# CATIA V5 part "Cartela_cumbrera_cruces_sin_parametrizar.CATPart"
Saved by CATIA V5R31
Part number: Cartela_param_pilar_dintel
Material "PLA": density 1240 kg/m3, Young's modulus 3.2e+09 Pa, Poisson ratio 0.331, thermal expansion 6.84e-05 1/K
Bounding box of the stored display mesh (mm): x -3.75 to 9.35, y -3.749 to 34.731, z -2 to 2
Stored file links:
  C:\Users\super\Desktop\LEGO\Cartela_cumbrera_cruces_sin_parametrizar.CATPart
  C:\Users\super\Desktop\LEGO\Cartela_hombro_cruces_sin_parametrizar.CATPart
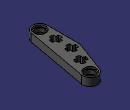
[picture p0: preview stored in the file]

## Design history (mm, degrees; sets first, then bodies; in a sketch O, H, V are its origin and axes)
Parameters
  Tipo_cartela = "dintel_dintel"
  Dist_pilares_estructura = 354.255 mm
  Long_dintel = 180 mm
  Diam_agujero = 5 mm
  N_lado_corto = 3
  Lado_cartela = 16 mm
  Espesor = 4 mm
  Angulo_cartela_pilar_dintel = 100.2497 deg {= acos((Dist_pilares_estructura/2)/Long_dintel)+90deg}
  Angulo_cartela_dintel_dintel = 159.5006 deg {= 2*(180deg-Angulo_cartela_pilar_dintel)}
  h = 10000 mm
  Altura_cartela = 10000 mm
  Angulo_cartela = 159.5006 deg
Set1 "REFERENCIAS"
  Plane1 "PLANO_CENTRAL": type OffsetPt, RefPlane XY plane of AxisSystem1, RefPoint vertex [element of Sketch1 | element of Sketch1]
  AxisSystem1: origin (0, 0, 0), X (1, 0, 0), Y (0, 1, 0), Z (0, 0, 1)
  Sketch1 "GUIA" on XY plane of AxisSystem1, origin (0, 0, 0), H (1, 0, 0), V (0, 1, 0)
    line L1 (0, 0) -> (0, 16)
    point P1 (0, 0)
    line L2 (0, 16) -> (5.6032, 30.9868)
    point P3 (5.6032, 30.9868)
    curve C1
    length L1 = 16 {= Lado_cartela}
    length L2 = 16 {= Lado_cartela}
    angle L1 L2 = 159.5006 {= Angulo_cartela}
    vertical: L1 V
    coincidence: P1 O
  Line1 "REF_LADO_LARGO": type PtPt, FirstPoint Sketch1.P3, SecondPoint vertex [YZ plane of AxisSystem1 | ZX plane of AxisSystem1 | XY plane of AxisSystem1]
  Point1 "PUNTO_MEDIO_LADO_LARGO": type OnCurve, Support Line1, Ratio 0.5
  Line2 "PERP_LADO_LARGO": type PtPt, FirstPoint vertex [element of Sketch1 | element of Sketch1], SecondPoint Point1
  Point2: type Between, FirstPoint vertex [element of Sketch1 | element of Sketch1], SecondPoint Sketch1.P3, Ratio 0.5
  Plane2: type OffsetPt, RefPlane Plane1, RefPoint Point2
  Plane3: type Angle, RefPlane Plane1, Direction Line2, Angle 90
  Point3: type Between, FirstPoint vertex [element of Sketch1 | element of Sketch1], SecondPoint Sketch1.P3, Ratio 0.5
  Plane4: type OffsetPt, RefPlane Plane1, RefPoint Point3
Body1 (main body), material "PLA"
  Sketch2 "BASE" on Plane1, origin (0, 16, 0), H (1, 0, 0), V (0, 1, 0)
    arc A1 centre (0, 0) radius 3.75 from (-3.5125, 1.3132) to (-3.75, 0) ccw
    point P1 (0, 0)
    point P2 (0, -16)
    arc A2 centre (0, -16) radius 3.75 from (-3.75, -16) to (3.6902, -16.6673) ccw
    point P3 (5.6032, 14.9868)
    arc A3 centre (5.6032, 14.9868) radius 3.75 from (9.2933, 14.3195) to (2.0906, 16.3001) ccw
    projected point E1 (5.6032, 14.9868) from Sketch1.P3
    projected point E2 (0, -16) from vertex [YZ plane of AxisSystem1 | ZX plane of AxisSystem1 | XY plane of AxisSystem1]
    line L1 (2.0906, 16.3001) -> (-3.5125, 1.3132)
    line L2 (9.2933, 14.3195) -> (3.6902, -16.6673)
    line L3 (-3.75, 0) -> (-3.75, -16)
    curve C1
    radius A3 = 3.75
    coincidence: P3 E1, P2 E2, P1 O
    tangency: L1 A3, L1 A1, L2 A3, L2 A2, L3 A1, L3 A2
    equal size: A1 A3, A3 A2
  Pad1 "CUERPO_BASE": profile Sketch2, direction (0, 0, 1), length 2 {= Espesor / 2}, mirrored extent
  Sketch3 "CRUZ" on Plane2, origin (2.8016, 23.4934, 0), H (-0.3502, -0.9367, 0), V (0.9367, -0.3502, 0)
    line L1 (-1, 2.2913) -> (-1, 1)
    line L2 (-1, 1) -> (-2.2913, 1)
    point P1 (-1, -1)
    line L3 (-2.2913, -1) -> (-1, -1)
    line L4 (-1, -1) -> (-1, -2.2913)
    line L5 (1, -2.2913) -> (1, -1)
    line L6 (1, -1) -> (2.2913, -1)
    point P3 (1, 1)
    line L7 (2.2913, 1) -> (1, 1)
    line L8 (1, 1) -> (1, 2.2913)
    arc A1 centre (0, 0) radius 2.5 from (1, 2.2913) to (-1, 2.2913) ccw
    point P4 (2.2913, -1)
    arc A2 centre (0, 0) radius 2.5 from (-2.2913, 1) to (-2.2913, -1) ccw
    arc A3 centre (0, 0) radius 2.5 from (2.2913, -1) to (2.2913, 1) ccw
    arc A4 centre (0, 0) radius 2.5 from (-1, -2.2913) to (1, -2.2913) ccw
    curve C1
    distance L3 L2 = 2
    distance L8 L1 = 2
    radius A1 = 2.5
    coincidence: P1 L1, P3 L5, P4 A1
    symmetry: L2 L3 H, L7 L6 H, L5 L4 V, L8 L1 V
    equal size: L6 L3, L4 L5, A4 A1, A1 A2, A2 A4, L1 L4, L5 L8, A3 A4, L7 L2, L6 L7
    horizontal: L7 H, L6 H
  Pocket1: profile Sketch3, direction (0, 0, -1), through (limit type 3), opposite side through (limit type 3)
  Mirror1: of Pocket1, about Plane3
  Sketch4 "CRUZ_CENTRAL" on Plane1, origin (0, 16, 0), H (-0.1779, -0.984, 0), V (-0.984, 0.1779, 0)
    line L1 (-1, 2.2913) -> (-1, 1)
    point P1 (-1, -1)
    line L2 (1, -2.2913) -> (1, -1)
    point P2 (1, 1)
    arc A1 centre (0, 0) radius 2.5 from (1, 2.2913) to (-1, 2.2913) ccw
    point P3 (2.2913, -1)
    line L3 (-1, 1) -> (-2.2913, 1)
    line L4 (-2.2913, -1) -> (-1, -1)
    line L5 (1, 1) -> (1, 2.2913)
    line L6 (1, -1) -> (2.2913, -1)
    line L7 (-1, -1) -> (-1, -2.2913)
    arc A2 centre (0, 0) radius 2.5 from (-1, -2.2913) to (1, -2.2913) ccw
    line L8 (2.2913, 1) -> (1, 1)
    arc A3 centre (0, 0) radius 2.5 from (-2.2913, 1) to (-2.2913, -1) ccw
    arc A4 centre (0, 0) radius 2.5 from (2.2913, -1) to (2.2913, 1) ccw
    curve C1
    distance L4 L3 = 2
    distance L5 L1 = 2
    radius A1 = 2.5
    coincidence: P1 L1, P2 L2, P3 A1
    equal size: L6 L4, L7 L2, A2 A1, A1 A3, A3 A2, L1 L7, L2 L5, A4 A2, L8 L3, L6 L8
    symmetry: L6 L8 H, L4 L3 H, L1 L5 V
    horizontal: L6 H, L8 H
  Pocket2: profile Sketch4, direction (0, 0, 1), through (limit type 3), opposite side through (limit type 3)
  Sketch5 on start face of Pad1, origin (6.6849, 29.8365, -2), H (1, 0, 0), V (0, -1, 0)
    point P1 (-1.0818, -1.1503)
    reference projected arc E1 centre (-1.0818, -1.1503) radius 3.75 from (-4.5943, -2.4635) to (2.6084, -0.483) ccw from edge [start face of Pad1 | face of Pad1 from Sketch2.A3]
    concentricity: E1 P1
  Hole1 "AGUJERO": placed by Sketch5, at (5.6032, 30.9868, -2) direction (0, 0, 1), diameter 5, through (limit type 3), counterbore diameter 6, counterbore depth 1
  RectPattern1: of Hole1, direction 1 instances 2, spacing 31.489, along Line1, direction 2 instances 3, spacing 4
  Mirror2: of Hole1, about Plane4
  Mirror3: of RectPattern1, about Plane1
Relations
  h = (Lado_cartela )* (sin(90deg-((Angulo_cartela_pilar_dintel )/2))) (deactivated)
  rule "Altura_cartela":
    /*Rule created by Jesus Arozamena*/
    if h >8mm	/*= Diam_agujero*2*/
    	Altura_cartela = h
    else
    	Altura_cartela = 0mm
  rule "Angulo_cartela":
    /*Rule created by Jesus Arozamena*/
    if Tipo_cartela  == "pilar_dintel"
    	Angulo_cartela  = Angulo_cartela_pilar_dintel
    else
    	Angulo_cartela  = Angulo_cartela_dintel_dintel
  rule "Existencia_agujero_lado_largo":
    /*Rule created by Jesus Arozamena 20/12/2023*/
    if Tipo_cartela =="dintel_dintel"
    	h = 10
    else
    	h = (Lado_cartela )* (sin(90deg-((Angulo_cartela_pilar_dintel )/2)))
